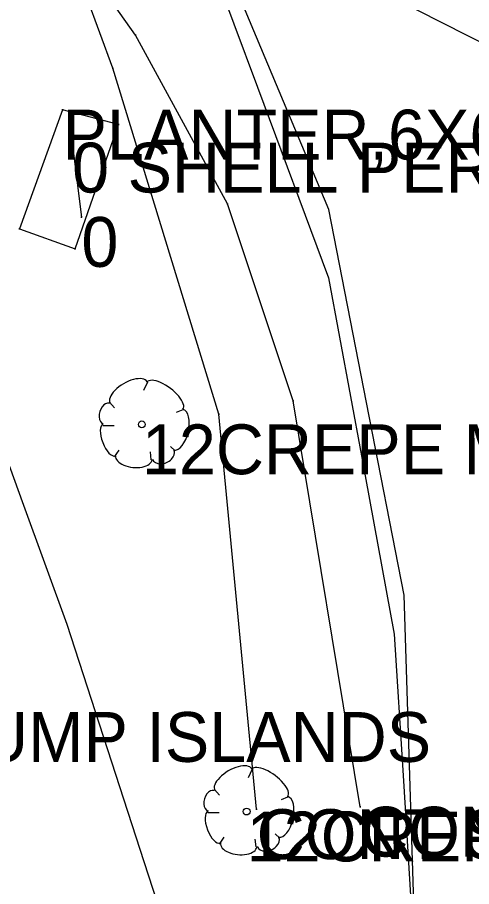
# Model space of a CAD drawing. Extents: x 997398 to 1003416, y 334596 to 337085.
# Drawn here: x 999549.7 to 999595.3, y 336485.6 to 336572.9 of the extents above; entities that cross this region are included whole.
import ezdxf

# ---------------------------------------------------------------- set-up
doc = ezdxf.new("R2010")
doc.units = 0
for name, color, linetype in [('S_BUILDING_ANNOT', 7, 'Continuous'), ('S_CURB', 7, 'Continuous'), ('S_EDGE_PAVEMENT', 7, 'Continuous'), ('S_FIBER_OPTIC_CABLE', 7, 'Continuous'), ('S_FIBER_OPTIC_CABLE_ANNOT', 7, 'Continuous'), ('S_GAS_UTILITIES', 7, 'Continuous'), ('S_GAS_UTILITIES_ANNOT', 7, 'Continuous'), ('S_GRD_PT_SYM', 7, 'Continuous'), ('S_LANDSCAPING', 7, 'Continuous'), ('S_LANDSCAPING_ANNOT', 7, 'Continuous'), ('S_MSC_PT_SYM', 7, 'Continuous'), ('S_SHOULDER', 7, 'Continuous'), ('S_SIGN', 7, 'Continuous'), ('S_SIGN_ANNOT', 7, 'Continuous'), ('S_TREE', 7, 'Continuous'), ('S_TREE_ANNOT', 7, 'Continuous'), ('S_UTL_PT_SYM', 7, 'Continuous')]:
    doc.layers.add(name, color=color, linetype=linetype)

msp = doc.modelspace()

# ---------------------------------------------------------------- linework, layer by layer
at = {"layer": 'S_CURB'}
msp.add_lwpolyline([(999499.195, 336612.107), (999510.843, 336606.264), (999522.491, 336600.42), (999529.871, 336580.074), (999537.252, 336559.729), (999541.599, 336547.787), (999545.946, 336535.846), (999550.293, 336523.904), (999554.639, 336511.963), (999561.972, 336489.389), (999569.304, 336466.815), (999574.031, 336451.55), (999576.612, 336447.065), (999581.429, 336446.088), (999583.605, 336447.704)], dxfattribs=at)
at = {"layer": 'S_EDGE_PAVEMENT'}
msp.add_lwpolyline([(999589.819, 336474.393), (999589.177, 336494.633), (999588.535, 336514.873), (999584.747, 336534.225), (999580.958, 336553.576), (999571.859, 336575.319), (999562.76, 336597.061), (999553.058, 336612.719), (999534.161, 336628.268), (999517.282, 336637.068), (999500.403, 336645.868)], dxfattribs=at)
at = {"layer": 'S_FIBER_OPTIC_CABLE'}
for p, q in [((999559.257, 336567.761), (999548.549, 336597.051)), ((999584.264, 336576.462), (999614.5, 336561.106)), ((999569.927, 336533.058), (999559.257, 336567.761)), ((999573.712, 336493.387), (999569.927, 336533.058))]:
    msp.add_line(p, q, dxfattribs=at)
at = {"layer": 'S_GAS_UTILITIES'}
for p, q in [((999561.547, 336571.091), (999551.374, 336585.533)), ((999570.77, 336554.155), (999561.547, 336571.091)), ((999577.4, 336534.371), (999570.77, 336554.155)), ((999584.12, 336493.636), (999577.4, 336534.371))]:
    msp.add_line(p, q, dxfattribs=at)
at = {"layer": 'S_GRD_PT_SYM'}
for points in [[(999554.217, 336563.605), (999554.217, 336563.655), (999554.217, 336563.605), (999554.167, 336563.605), (999554.217, 336563.605), (999554.217, 336563.555), (999554.217, 336563.605), (999554.267, 336563.605)], [(999559.836, 336562.126), (999559.836, 336562.176), (999559.836, 336562.126), (999559.786, 336562.126), (999559.836, 336562.126), (999559.836, 336562.076), (999559.836, 336562.126), (999559.886, 336562.126)], [(999549.88, 336551.652), (999549.88, 336551.702), (999549.88, 336551.652), (999549.83, 336551.652), (999549.88, 336551.652), (999549.88, 336551.602), (999549.88, 336551.652), (999549.93, 336551.652)], [(999555.463, 336549.643), (999555.463, 336549.693), (999555.463, 336549.643), (999555.413, 336549.643), (999555.463, 336549.643), (999555.463, 336549.593), (999555.463, 336549.643), (999555.513, 336549.643)]]:
    msp.add_lwpolyline(points, dxfattribs=at)
at = {"layer": 'S_LANDSCAPING'}
for p, q in [((999554.217, 336563.605), (999549.88, 336551.652)), ((999559.836, 336562.126), (999554.217, 336563.605)), ((999555.463, 336549.643), (999559.836, 336562.126)), ((999549.88, 336551.652), (999555.463, 336549.643))]:
    msp.add_line(p, q, dxfattribs=at)
at = {"layer": 'S_MSC_PT_SYM'}
for points in [[(999555.169, 336560.292), (999555.169, 336560.342), (999555.169, 336560.292), (999555.118, 336560.292), (999555.169, 336560.292), (999555.169, 336560.242), (999555.169, 336560.292), (999555.219, 336560.292)], [(999556.103, 336552.832), (999556.103, 336552.882), (999556.103, 336552.832), (999556.052, 336552.832), (999556.103, 336552.832), (999556.103, 336552.782), (999556.103, 336552.832), (999556.153, 336552.832)]]:
    msp.add_lwpolyline(points, dxfattribs=at)
at = {"layer": 'S_SHOULDER'}
msp.add_lwpolyline([(999499.085, 336645.203), (999516.842, 336635.736), (999534.599, 336626.269), (999551.478, 336608.213), (999559.078, 336596.6), (999566.677, 336584.986), (999573.807, 336565.854), (999580.936, 336546.722), (999584.243, 336528.845), (999587.549, 336510.968), (999588.428, 336496.758), (999589.307, 336482.548)], dxfattribs=at)
at = {"layer": 'S_SIGN'}
msp.add_line((999555.169, 336560.292), (999556.103, 336552.832), dxfattribs=at)
at = {"layer": 'S_TREE'}
for p, q in [((999562.736, 336536.262), (999562.348, 336535.41)), ((999558.938, 336534.247), (999559.442, 336533.666)), ((999566.301, 336533.472), (999565.642, 336533.201)), ((999558.28, 336531.922), (999559.403, 336531.922)), ((999559.442, 336528.745), (999559.907, 336529.442)), ((999565.526, 336529.365), (999565.061, 336529.791)), ((999563.123, 336528.474), (999563.046, 336529.249)), ((999573.265, 336497.396), (999572.878, 336496.544)), ((999569.468, 336495.381), (999569.972, 336494.8)), ((999576.83, 336494.606), (999576.172, 336494.335)), ((999568.809, 336493.056), (999569.933, 336493.056)), ((999576.055, 336490.499), (999575.59, 336490.925)), ((999569.972, 336489.879), (999570.437, 336490.576)), ((999573.653, 336489.607), (999573.575, 336490.382))]:
    msp.add_line(p, q, dxfattribs=at)
for centre in [(999562.178, 336532.017), (999572.707, 336493.151)]:
    msp.add_circle(centre, 0.341, dxfattribs=at)
for centre, major_axis, ratio, start_param, end_param in [((999560.842, 336535.219), (1.857, 1.085), 0.471018, 0, 3.141593), ((999564.496, 336534.896), (-1.813, 1.36), 0.405113, 3.141593, 6.283186), ((999558.607, 336533.105), (0.305, 1.027), 0.646762, 0, 3.141593), ((999565.852, 336531.487), (0.458, 2.04), 0.482994, 3.141593, 6.283185), ((999558.912, 336530.454), (-0.611, 1.596), 0.420543, 6.283185, 9.424777), ((999564.33, 336528.966), (1.092, 0.462), 0.711534, 3.141592, 6.283185), ((999561.373, 336528.673), (-1.832, 0.194), 0.529943, 0, 3.141593), ((999571.371, 336496.353), (1.857, 1.085), 0.471018, 0, 3.141593), ((999575.026, 336496.03), (-1.813, 1.36), 0.405113, 3.141593, 6.283186), ((999569.137, 336494.238), (0.305, 1.027), 0.646762, 0, 3.141593), ((999576.381, 336492.621), (0.458, 2.04), 0.482994, 3.141593, 6.283185), ((999569.442, 336491.588), (-0.611, 1.596), 0.420543, 6.283185, 9.424777), ((999571.903, 336489.807), (-1.832, 0.194), 0.529943, 0, 3.141593), ((999574.86, 336490.1), (1.092, 0.462), 0.711534, 3.141592, 6.283185)]:
    msp.add_ellipse(centre, major_axis=major_axis, ratio=ratio, start_param=start_param, end_param=end_param, dxfattribs=at)
at = {"layer": 'S_UTL_PT_SYM'}
for points in [[(999561.547, 336571.091), (999561.547, 336571.141), (999561.547, 336571.091), (999561.497, 336571.091), (999561.547, 336571.091), (999561.547, 336571.041), (999561.547, 336571.091), (999561.597, 336571.091)], [(999559.257, 336567.761), (999559.257, 336567.811), (999559.257, 336567.761), (999559.207, 336567.761), (999559.257, 336567.761), (999559.257, 336567.711), (999559.257, 336567.761), (999559.307, 336567.761)], [(999570.77, 336554.155), (999570.77, 336554.205), (999570.77, 336554.155), (999570.72, 336554.155), (999570.77, 336554.155), (999570.77, 336554.105), (999570.77, 336554.155), (999570.82, 336554.155)], [(999577.4, 336534.371), (999577.4, 336534.421), (999577.4, 336534.371), (999577.35, 336534.371), (999577.4, 336534.371), (999577.4, 336534.321), (999577.4, 336534.371), (999577.45, 336534.371)], [(999569.927, 336533.058), (999569.927, 336533.108), (999569.927, 336533.058), (999569.877, 336533.058), (999569.927, 336533.058), (999569.927, 336533.008), (999569.927, 336533.058), (999569.977, 336533.058)], [(999584.12, 336493.636), (999584.12, 336493.686), (999584.12, 336493.636), (999584.07, 336493.636), (999584.12, 336493.636), (999584.12, 336493.586), (999584.12, 336493.636), (999584.17, 336493.636)], [(999573.712, 336493.387), (999573.712, 336493.437), (999573.712, 336493.387), (999573.662, 336493.387), (999573.712, 336493.387), (999573.712, 336493.337), (999573.712, 336493.387), (999573.762, 336493.387)]]:
    msp.add_lwpolyline(points, dxfattribs=at)

# ---------------------------------------------------------------- texts
at = {"layer": 'S_BUILDING_ANNOT'}
msp.add_text('CANOPY OVER PUMP ISLANDS', height=5, dxfattribs=at).set_placement((999490.557, 336498.139))
at = {"layer": 'S_FIBER_OPTIC_CABLE_ANNOT'}
msp.add_text('CONT SOUTH', height=5, dxfattribs=at).set_placement((999573.712, 336488.387))
at = {"layer": 'S_GAS_UTILITIES_ANNOT'}
msp.add_text('CONT SOUTH', height=5, dxfattribs=at).set_placement((999584.12, 336488.636))
at = {"layer": 'S_LANDSCAPING_ANNOT'}
msp.add_text('PLANTER,6X6 WOOD TIMBERS', height=5, dxfattribs=at).set_placement((999554.217, 336558.605))
at = {"layer": 'S_SIGN_ANNOT'}
for s, p in [('0 SHELL PERM. NUM. TY:8"SQ STEEL', (999555.169, 336555.292)), ('0', (999556.103, 336547.832))]:
    msp.add_text(s, height=5, dxfattribs=at).set_placement(p)
at = {"layer": 'S_TREE_ANNOT'}
for p in [(999562.178, 336527.017), (999572.707, 336488.151)]:
    msp.add_text('12CREPE MYRTLE', height=5, dxfattribs=at).set_placement(p)

doc.saveas('drawing.dxf')
